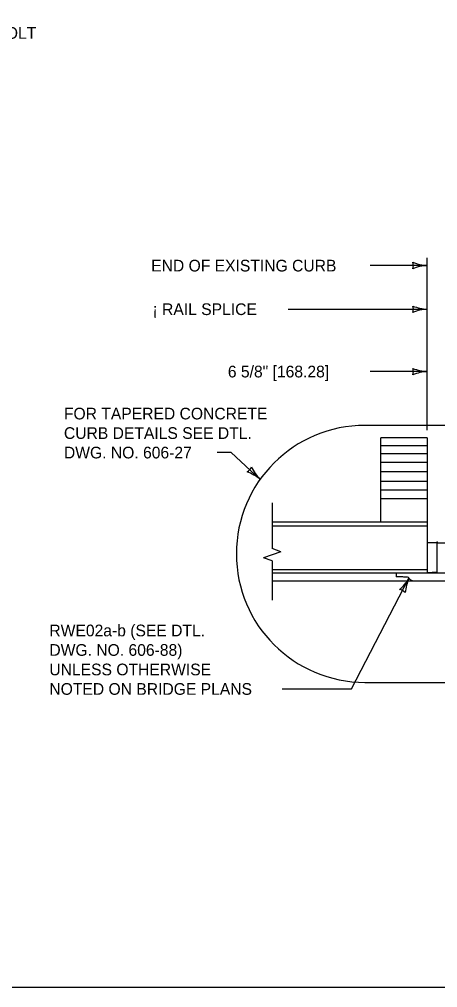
# Model space of a CAD drawing. Extents: x 49991.4 to 50021, y 49987.6 to 50011.4.
# Drawn here: x 50007.522 to 50009.666, y 49987.799 to 49992.766 of the extents above; entities that cross this region are included whole.
import ezdxf

# ---------------------------------------------------------------- set-up
doc = ezdxf.new("R2010")
doc.units = 0
for name, color, linetype in [('Level 1', 7, 'Continuous'), ('Level 2', 7, 'Continuous'), ('Level 3', 7, 'Continuous'), ('Level 4', 7, 'Continuous'), ('Level 6', 7, 'Continuous'), ('Level 7', 7, 'Continuous')]:
    doc.layers.add(name, color=color, linetype=linetype)

msp = doc.modelspace()

# ---------------------------------------------------------------- linework, layer by layer
at = {"layer": 'Level 1'}
for p, q in [((50009.6135, 49990.6191), (50009.3759, 49990.6191)), ((50009.3759, 49990.1862), (50009.3759, 49990.6191)), ((50009.6135, 49990.6191), (50009.6135, 49990.0861)), ((50009.6135, 49990.5789), (50009.3759, 49990.5789)), ((50009.6135, 49990.5366), (50009.3759, 49990.5366)), ((50009.6135, 49990.492), (50009.3759, 49990.492)), ((50009.6135, 49990.4457), (50009.3759, 49990.4457)), ((50009.6135, 49990.3957), (50009.3759, 49990.3957)), ((50009.6135, 49990.3511), (50009.3759, 49990.3511)), ((50009.6135, 49990.307), (50009.3759, 49990.307)), ((50009.6135, 49990.1862), (50008.8185, 49990.1862)), ((50009.6135, 49990.1667), (50008.8185, 49990.1667)), ((50009.6135, 49990.0861), (50009.6135, 49989.9261)), ((50009.6619, 49990.0861), (50009.6619, 49989.9261)), ((50009.6619, 49990.0861), (50009.6661, 49990.0861)), ((50009.6661, 49990.0808), (50009.6661, 49990.0861)), ((50009.6619, 49990.0808), (50009.6135, 49990.0808)), ((50009.6661, 49990.0808), (50009.7377, 49990.0808)), ((50009.6135, 49989.9417), (50008.8185, 49989.9417)), ((50008.8185, 49989.9261), (50013.9981, 49989.9261)), ((50008.8185, 49989.886), (50013.9981, 49989.886)), ((50009.4535, 49989.9261), (50009.4535, 49989.9054)), ((50009.6619, 49989.9296), (50009.6135, 49989.9261))]:
    msp.add_line(p, q, dxfattribs=at)
msp.add_lwpolyline([(49999.3835, 49998.9992), (50016.7501, 49998.9992), (50016.7501, 49987.7988), (49999.3835, 49987.7988)], close=True, dxfattribs=at)
at = {"layer": 'Level 3'}
for p, q in [((50009.6135, 49990.6591), (50009.6135, 49991.5426)), ((50009.6135, 49991.5027), (50009.32, 49991.5027)), ((50008.8995, 49991.2792), (50009.6135, 49991.2792)), ((50009.6135, 49990.9592), (50009.321, 49990.9592)), ((50008.6081, 49990.5437), (50008.5361, 49990.5437)), ((50008.6081, 49990.5437), (50008.7567, 49990.4062)), ((50009.2246, 49989.331), (50009.5197, 49989.8991)), ((50008.8689, 49989.331), (50009.2246, 49989.331))]:
    msp.add_line(p, q, dxfattribs=at)
for centre, radius, start, end in [((50009.4886, 49991.5039), 0.0534, 341.5738, 17.2962), ((50009.6225, 49991.2757), 0.2271, 92.2623, 111.5122), ((50009.6246, 49991.7191), 0.2167, 246.891, 267.0745), ((50009.6225, 49991.4957), 0.2167, 247.456, 267.6395), ((50009.4886, 49991.2792), 0.0534, 342.1388, 17.8612), ((50009.6248, 49991.0523), 0.2271, 92.8273, 112.0772), ((50009.6225, 49991.1757), 0.2167, 247.456, 267.6395), ((50009.4886, 49990.9592), 0.0534, 342.1388, 17.8612), ((50009.6248, 49990.7323), 0.2271, 92.8273, 112.0772), ((50008.6626, 49990.4932), 0.0548, 299.37, 335.0924), ((50008.6072, 49990.2275), 0.233, 50.0585, 69.3084), ((50008.9143, 49990.563), 0.2223, 204.6872, 224.8707), ((50009.3317, 49990.0069), 0.2167, 309.9961, 330.1796), ((50009.7262, 49989.8044), 0.2271, 155.3674, 174.6172), ((50009.4621, 49989.7882), 0.0534, 44.6789, 80.4012)]:
    msp.add_arc(centre, radius, start, end, dxfattribs=at)
at = {"layer": 'Level 4'}
for p, q in [((50010.4837, 49990.6834), (50009.294, 49990.6834)), ((50009.294, 49989.365), (50009.3032, 49989.3649)), ((50009.3032, 49989.3649), (50010.4928, 49989.3649))]:
    msp.add_line(p, q, dxfattribs=at)
msp.add_arc((50009.294, 49990.0242), 0.6592, 90, 270, dxfattribs=at)
at = {"layer": 'Level 6'}
for p, q in [((50008.8185, 49990.2862), (50008.8185, 49990.0511)), ((50008.8631, 49990.0353), (50008.8185, 49990.0511)), ((50008.8631, 49990.0353), (50008.8185, 49990.0195)), ((50008.8185, 49990.0195), (50008.774, 49990.0037)), ((50008.8185, 49989.9879), (50008.774, 49990.0037)), ((50008.8185, 49989.9879), (50008.8185, 49989.7861))]:
    msp.add_line(p, q, dxfattribs=at)
at = {"layer": 'Level 7'}
msp.add_line((50009.4886, 49989.9054), (50009.4535, 49989.9054), dxfattribs=at)
msp.add_spline([(50009.538, 49989.886), (50009.532, 49989.8878), (50009.5258, 49989.892), (50009.5206, 49989.8981), (50009.5165, 49989.9022), (50009.5072, 49989.9043), (50009.4886, 49989.9054)], degree=3, dxfattribs=at)

# ---------------------------------------------------------------- texts
at = {"layer": 'Level 2'}
for s, p in [('1" [25.4] DIA. HOLE FOR 7/8" [M22] DIA. BOLT', (50005.9067, 49992.6663)), ('END OF EXISTING CURB', (50008.1982, 49991.4727)), ('¡ RAIL SPLICE', (50008.2049, 49991.2492)), ('6 5/8" [168.28]', (50008.5912, 49990.9292)), ('FOR TAPERED CONCRETE', (50007.7508, 49990.7137)), ('CURB DETAILS SEE DTL.', (50007.7508, 49990.6137)), ('DWG. NO. 606-27', (50007.7508, 49990.5137)), ('RWE02a-b (SEE DTL.', (50007.6762, 49989.601)), ('DWG. NO. 606-88)', (50007.6762, 49989.501)), ('UNLESS OTHERWISE', (50007.6762, 49989.401)), ('NOTED ON BRIDGE PLANS', (50007.6762, 49989.301))]:
    msp.add_text(s, height=0.06, dxfattribs=at).set_placement(p)

doc.saveas('drawing.dxf')
